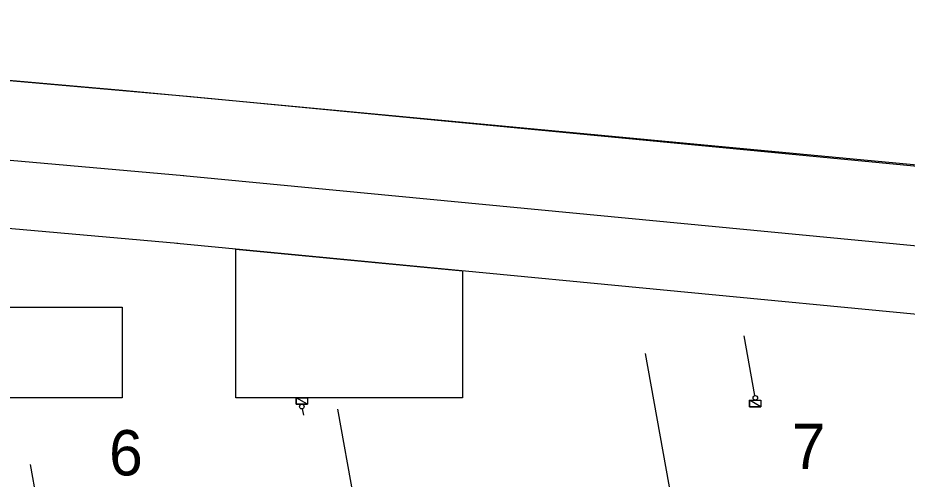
# Model space of a CAD drawing. Extents: x -263964 to -263544, y -1242317 to -1242020.
# Drawn here: x -263871.58 to -263832.36, y -1242081.98 to -1242061.62 of the extents above; entities that cross this region are included whole.
import ezdxf

# ---------------------------------------------------------------- set-up
doc = ezdxf.new("R2010")
doc.units = 0
doc.layers.add('KFA_KOORDINACNA_SITUACIA_DSP_SEDA', color=7, linetype='Continuous')
doc.layers.add('KFA_SO_50-1-II_BODY', color=7, linetype='Continuous')

msp = doc.modelspace()

# ---------------------------------------------------------------- linework, layer by layer
at = {"layer": 'KFA_KOORDINACNA_SITUACIA_DSP_SEDA'}
for p, q in [((-263866.964, -1242064.823), (-263895.455, -1242062.322)), ((-263816.79, -1242069.539), (-263866.964, -1242064.823)), ((-263765.318, -1242074.565), (-263863.949, -1242065.106)), ((-263765.364, -1242078.076), (-263864.283, -1242068.59)), ((-263765.366, -1242081.09), (-263864.57, -1242071.577)), ((-263861.968, -1242078.382), (-263861.968, -1242071.826)), ((-263861.968, -1242071.826), (-263851.968, -1242072.785)), ((-263851.968, -1242072.785), (-263851.968, -1242078.382)), ((-263839.074, -1242078.29), (-263839.551, -1242075.646)), ((-263841.881, -1242087.633), (-263843.905, -1242076.433)), ((-263851.968, -1242078.382), (-263861.968, -1242078.382)), ((-263859.303, -1242078.673), (-263859.303, -1242078.383)), ((-263859.303, -1242078.383), (-263858.803, -1242078.383)), ((-263858.803, -1242078.673), (-263859.303, -1242078.383)), ((-263858.803, -1242078.673), (-263859.303, -1242078.383)), ((-263859.303, -1242078.383), (-263859.303, -1242078.673)), ((-263858.803, -1242078.383), (-263858.803, -1242078.673)), ((-263858.803, -1242078.673), (-263859.303, -1242078.673)), ((-263859.303, -1242078.673), (-263858.803, -1242078.673)), ((-263839.306, -1242078.779), (-263839.306, -1242078.489)), ((-263839.306, -1242078.489), (-263838.806, -1242078.489)), ((-263838.806, -1242078.779), (-263839.306, -1242078.489)), ((-263838.806, -1242078.779), (-263839.306, -1242078.489)), ((-263839.306, -1242078.489), (-263839.306, -1242078.779)), ((-263838.806, -1242078.779), (-263839.306, -1242078.779)), ((-263839.306, -1242078.779), (-263838.806, -1242078.779)), ((-263838.806, -1242078.489), (-263838.806, -1242078.779)), ((-263859.035, -1242078.872), (-263858.983, -1242079.157)), ((-263855.881, -1242087.633), (-263857.462, -1242078.882)), ((-263869.881, -1242087.633), (-263871.02, -1242081.332))]:
    msp.add_line(p, q, dxfattribs=at)
for points in [[(-263863.949, -1242065.106), (-263895.455, -1242062.322), (-263915.197, -1242060.921), (-263926.771, -1242063.254), (-263950.745, -1242062.149), (-263959.468, -1242059.534)], [(-263864.257, -1242068.593), (-263895.733, -1242065.811), (-263914.971, -1242064.445), (-263926.501, -1242066.77), (-263951.337, -1242065.625), (-263959.611, -1242063.145)], [(-263864.521, -1242071.581), (-263895.971, -1242068.802), (-263914.777, -1242067.467), (-263926.271, -1242069.784), (-263951.845, -1242068.605), (-263959.611, -1242066.277)]]:
    msp.add_lwpolyline(points, dxfattribs=at)
msp.add_lwpolyline([(-263881.968, -1242074.382), (-263866.968, -1242074.382), (-263866.968, -1242078.382), (-263881.968, -1242078.382)], close=True, dxfattribs=at)
for centre in [(-263839.056, -1242078.389), (-263859.053, -1242078.773)]:
    msp.add_circle(centre, 0.1, dxfattribs=at)

# ---------------------------------------------------------------- texts
at = {"layer": 'KFA_SO_50-1-II_BODY'}
for s, p in [('7', (-263837.45, -1242081.531)), ('6', (-263867.553, -1242081.81))]:
    msp.add_text(s, height=2, dxfattribs=at).set_placement(p)

doc.saveas('drawing.dxf')
